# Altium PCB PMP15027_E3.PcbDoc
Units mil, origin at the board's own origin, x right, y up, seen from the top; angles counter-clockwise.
Board outline 3310 x 2510 mil, 4 copper layers (Top Layer, Inner Layer 1, Inner Layer 2, Bottom Layer), stack 61.2 mil thick; 79 components, 38 nets, 184 pads, 168 vias.
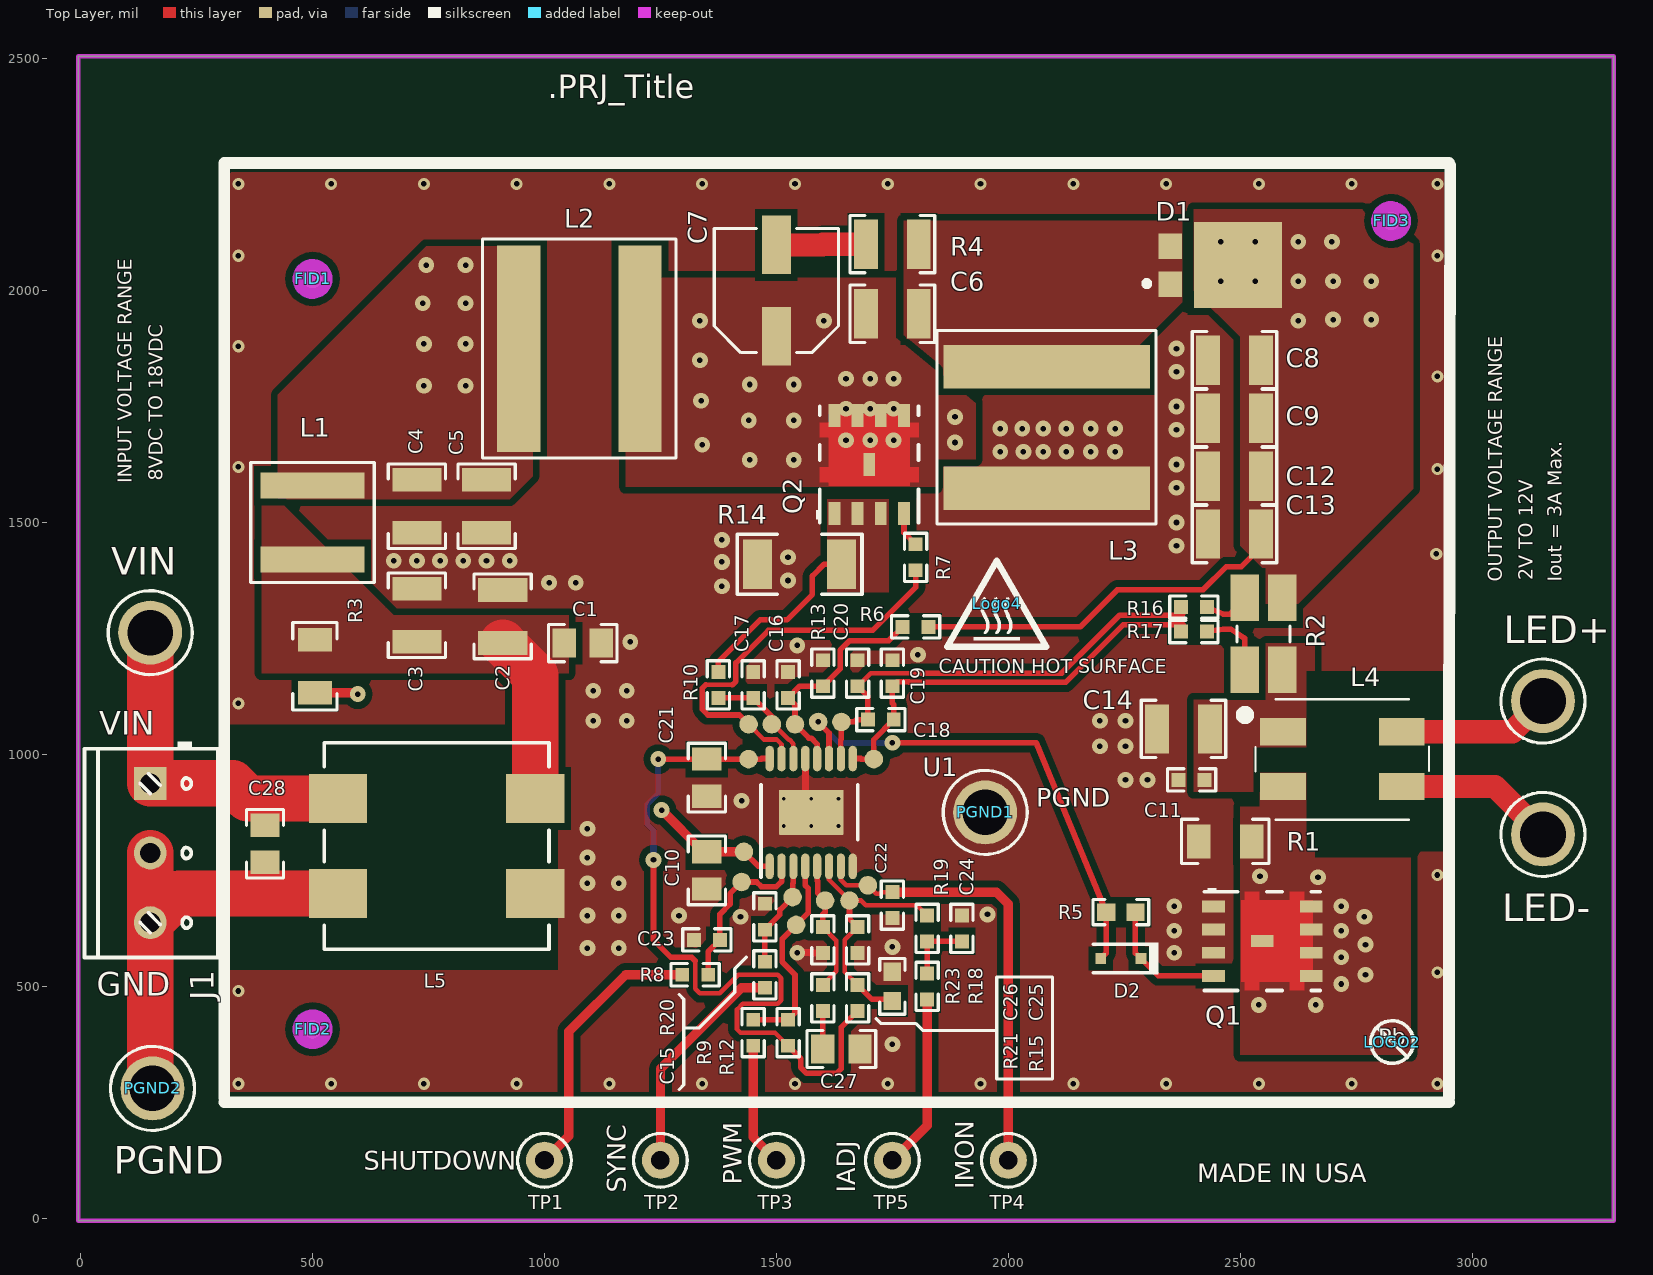
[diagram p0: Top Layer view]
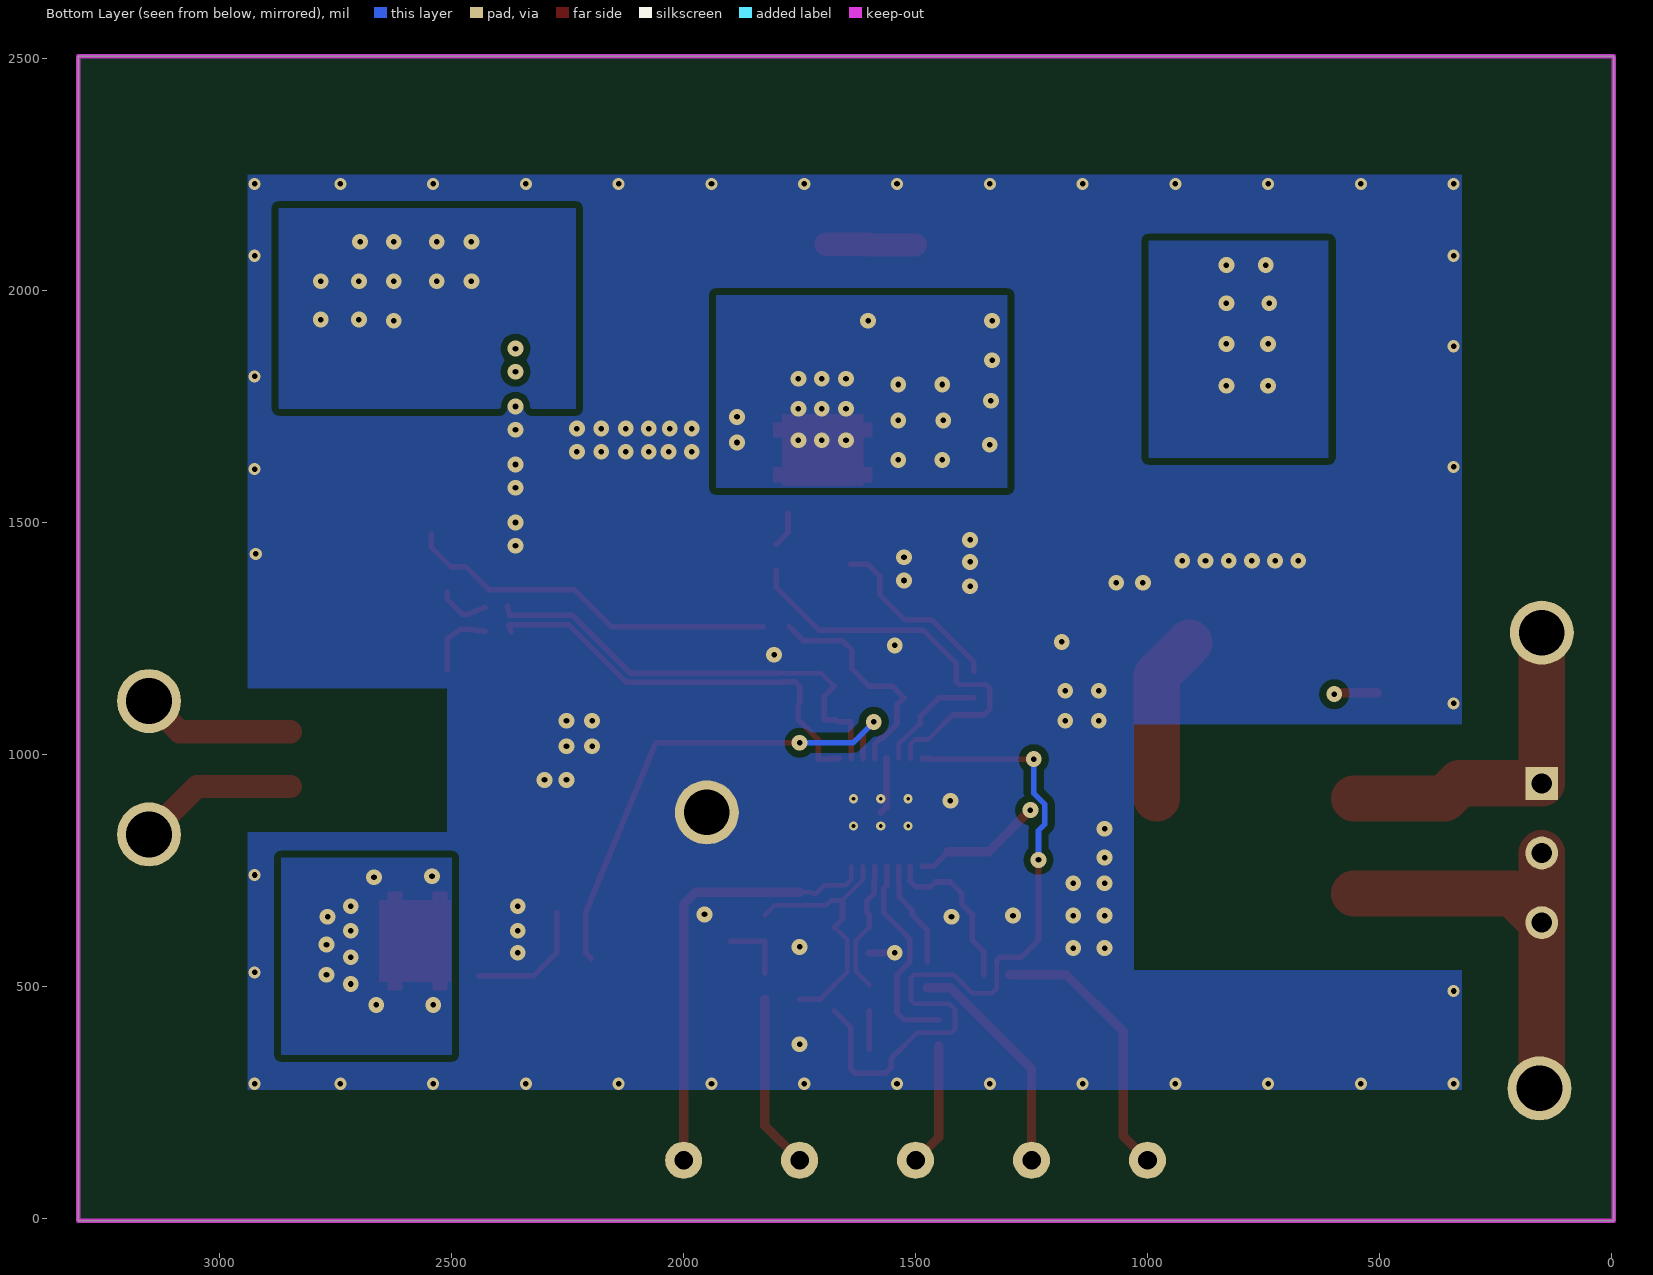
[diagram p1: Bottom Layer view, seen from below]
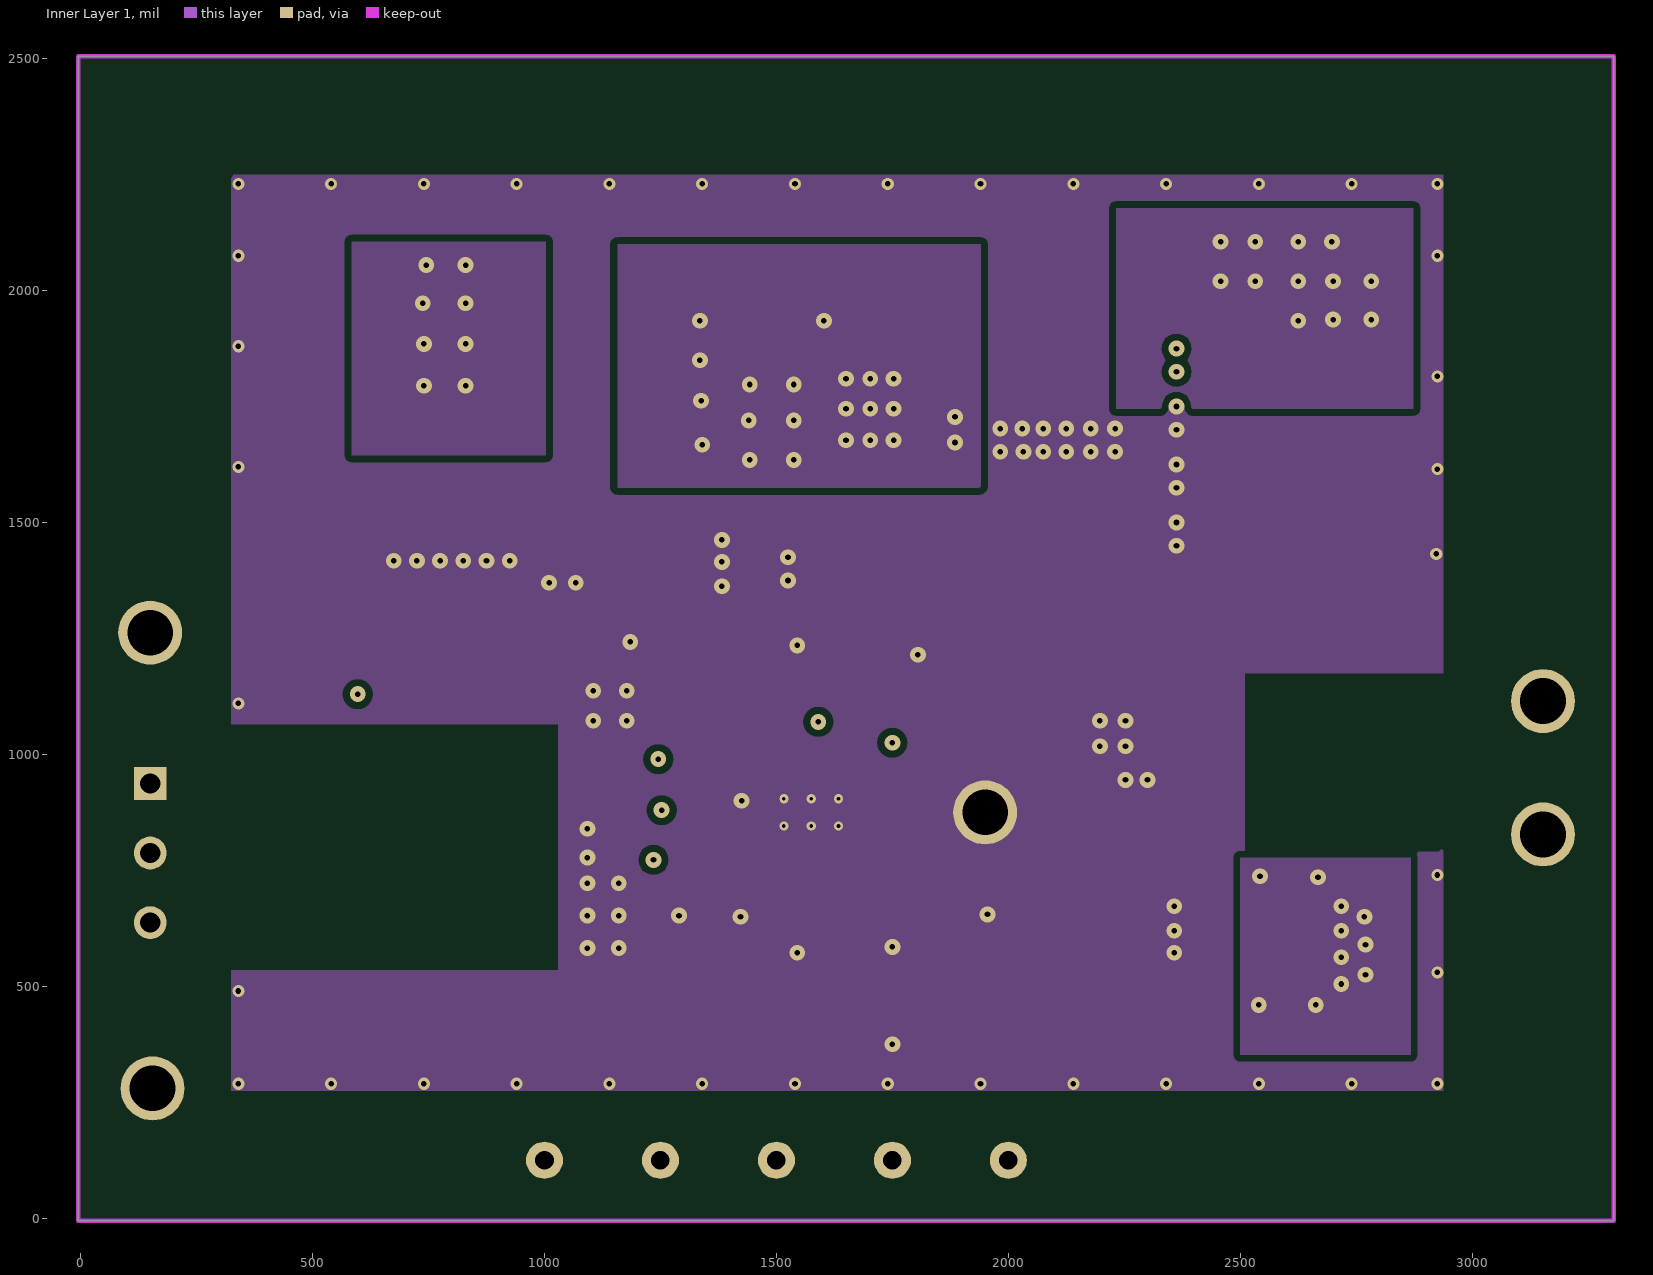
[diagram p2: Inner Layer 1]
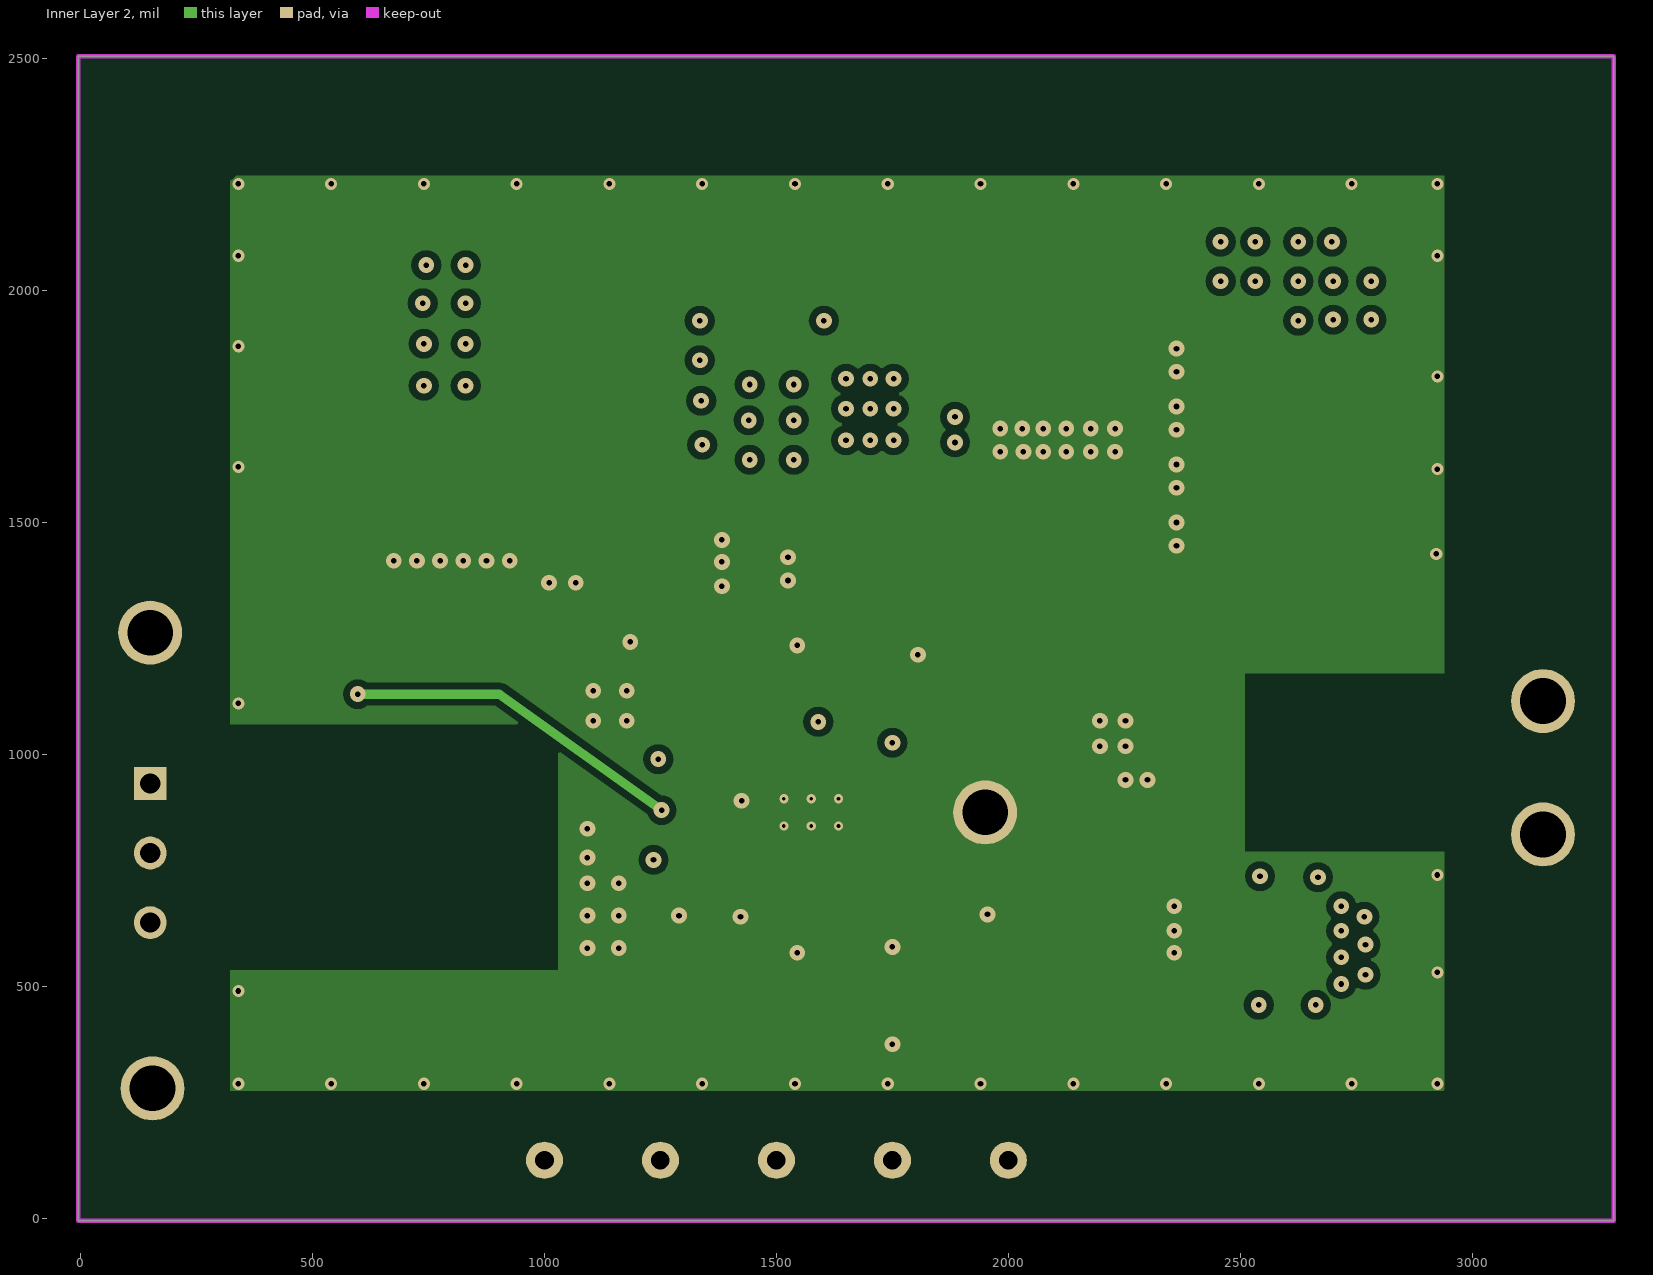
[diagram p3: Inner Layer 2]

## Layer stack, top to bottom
Top Solder: solder mask 0.4, Solder Resist, Dk 3.5
Top Layer: signal copper 1.4
Dielectric1: prepreg 8, Dk 4.2
Inner Layer 1: signal copper 2.8
Dielectric 3: core 36.8, Dk 4.2
Inner Layer 2: signal copper 2.8
Dielectric 2: prepreg 8, Dk 4.2
Bottom Layer: signal copper 1.4
Bottom Solder: solder mask 0.4, Solder Resist, Dk 3.5

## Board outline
-5,-5 -5,2505 3305,2505 3305,-5

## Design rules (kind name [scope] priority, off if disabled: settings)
AcuteAngle [All] p1: minimum=4.50000000000000E+0001 checktracksonly=FALSE
AssemblyTestPointUsage [All] p1: valid=2
Clearance Clearance_Keepouts [((IsTrack Or IsArc) And Not InPoly) And IsFree and IsKeepOut vs ((IsTrack Or IsArc) And Not InPoly) And IsFree and IsKeepOut] p1: gap=0
Clearance Clearance_BoardEdge_MountingHoles [OnCopper and InComponentClass('Mounting Holes') vs IsKeepOut] p2: gap=40
Clearance Clearance_BoardEdge_Poly [OnCopper and InPoly vs IsKeepOut] p3: gap=15
Clearance Clearance_BoardEdge [OnCopper and Not InComponentClass('Logo') and not InComponentClass('FiducialMark') and not InRegion(1000,500,4000,800) and Not IsKeepout vs IsKeepOut] p4: gap=25
Clearance Clearance_Poly [InPolygon] p5: gap=15
Clearance [All] p6: gap=7.87
ComponentClearance ComponentClearance_Logos [InComponentClass('Logo')] p1: gap=-1 collisioncheckmode=3 verticalgap=-1 showdistances=FALSE
ComponentClearance [All] p2: gap=5 collisioncheckmode=3 verticalgap=5 showdistances=FALSE
DiffPairsRouting [All] p1: maxlimit=100 minlimit=10 mostfreqgap=10 toplayer_minwidth=15 toplayer_maxwidth=15 toplayer_prefwidth=15 midlayer1_minwidth=15 midlayer1_maxwidth=15 midlayer1_prefwidth=15 midlayer2_minwidth=15 midlayer2_maxwidth=15 midlayer2_prefwidth=15 bottomlayer_minwidth=15 bottomlayer_maxwidth=15 bottomlayer_prefwidth=15 maxuncoupledlength=1000
FabricationTestPointUsage TestPointUsage [All] p1: valid=2 allowmultiple=FALSE
FabricationTestpoint Testpoint [All] p1: side=3 testpointundercomponent=TRUE minsize=40 maxsize=100 preferedsize=60 minholesize=0 maxholesize=40 preferedholesize=32 testpointgrid=1 allowsidetop=TRUE allowsidebottom=TRUE usegrid=TRUE gridtolerance=0.01
FanoutControl Fanout_LCC [IsLCC] p1: bgadir=Out bgaviamode=Centered fanoutstyle=Auto fanoutdirection=Alternating viagrid=1 // Fanout_LCC (Default Rule)
FanoutControl Fanout_BGA [IsBGA] p2: bgadir=Out bgaviamode=Centered fanoutstyle=Auto fanoutdirection=Alternating viagrid=1 // Fanout_BGA (Default Rule)
FanoutControl Fanout_Default [All] p4: bgadir=Out bgaviamode=Centered fanoutstyle=Auto fanoutdirection=Alternating viagrid=1 // Fanout_Default (Default Rule)
FanoutControl Fanout_Small [(CompPinCount < 5)] p5: bgadir=Out bgaviamode=Centered fanoutstyle=Auto fanoutdirection=OutThenIn viagrid=1 // Fanout_Small (Default Rule)
HoleSize [All] p1: absolutevalues=TRUE maxlimit=251 minlimit=7.87 maxpercent=80.000 minpercent=20.000
MinimumAnnularRing MinimumAnnularRing_U1 [InComponent('U1')] p1: minimumring=0
MinimumAnnularRing MinimumAnnularRing_ThermalPadVias [IsVia and InAnyComponent] p2: minimumring=2.5
MinimumAnnularRing [All] p3: minimumring=5
MinimumSolderMaskSliver MinimumSolderMaskSliver_Logo [InComponentClass('Logo') vs InComponentClass('Logo')] p1: minsoldermaskwidth=0.7
MinimumSolderMaskSliver [All] p2: minsoldermaskwidth=5
PlaneConnect [All] p1: planeconnectstyle=Relief reliefexpansion=10 reliefentries=4 reliefconductorwidth=10 reliefairgap=10
PolygonConnect [All] p1: connectstyle=Direct reliefconductorwidth=10 reliefentries=4 polygonreliefangle="90 Angle" airgapwidth=10
RoutingVias RoutingVias_U1_Q1 [InComponent('U1') OR InComponent('Q1')] p1: holewidth=28 width=50 viastyle="Through Hole" minholewidth=7.87 minwidth=15.75 maxholewidth=28 maxwidth=50
RoutingVias ThermalPadVias [IsVia and InAnyComponent] p2: holewidth=7.87 width=19.68 viastyle="Through Hole" minholewidth=7.87 minwidth=19.68 maxholewidth=12.99 maxwidth=23.62
RoutingVias [All] p3: holewidth=12 width=34 viastyle="Through Hole" minholewidth=7.87 minwidth=20 maxholewidth=40 maxwidth=65
SilkToBoardRegionClearance [Not ((IsComment or IsDesignator) And (Hide <> 'False')) and not InRegion(1000,500,4000,800)] p1:
SilkToSilkClearance SilkToSilkClearance_Pb-FreeLogo [(HasFootprint('Pb-Free_Overlay_Medium') OR HasFootprint('Pb-Free_Overlay_Small')) vs (HasFootprint('Pb-Free_Overlay_Medium') OR HasFootprint('Pb-Free_Overlay_Small'))] p1: silktosilkclearance=0
SilkToSilkClearance [All] p2: silktosilkclearance=3
SilkToSolderMaskClearance SilkToSolderMaskClearance_J1 [InComponent('J1')] p1: minsilkscreentomaskgap=-1 clearancetoexposedcopper=TRUE
SilkToSolderMaskClearance [IsPad] p2: minsilkscreentomaskgap=5 clearancetoexposedcopper=TRUE
SolderMaskExpansion [All] p1: expansion=0
Width [All] p1: maxlimit=100 minlimit=6 preferedwidth=10 toplayer_minwidth=7 toplayer_prefwidth=7 bottomlayer_minwidth=7 bottomlayer_prefwidth=7 minimp=50.000000 maximp=50.000000 favimp=50.000000 checkconnectedcopper=TRUE
15 further rules are at their usual default settings.

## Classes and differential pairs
component class PMP15027_E3: C1 C2 C3 C4 C5 C6 C7 C8 C9 C10 C11 C12 C13 C14 C15 C16 C17 C18 C19 C20 C21 C22 C23 C24 C25 C26 C27 C28 D1 D2 J1 L1 L2 L3 L4 L5 LED+ LED- Logo4 PGND1 PGND2 Q1 Q2 R1 R2 R3 R4 R5 R6 R7 R8 R9 R10 R12 R13 R14 R15 R16 R17 R18 R19 R20 R21 R23 TP1 TP2 TP3 TP4 TP5 U1 VIN
component class PMP15027_E3_Hardware: FID1 FID2 FID3 LOGO2 ZZ1 ZZ2 ZZ3 ZZ4
component class FiducialMark: FID1 FID2 FID3
component class AssemblyNote: ZZ1 ZZ2 ZZ3 ZZ4

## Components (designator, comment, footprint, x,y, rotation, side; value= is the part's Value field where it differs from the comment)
C1 "C2012X7R2A104K" 0805_HV 1082.5,1240 r0 top
C2 "C3225X7S2A475K200AE" 1210 910,1297.5 r90 top
C3 "CGA6P3X7S1H106K250AB" 1210 725,1300 r90 top
C4 "CGA6P3X7S1H106K250AB" 1210 725,1535 r270 top
C5 "CGA6P3X7S1H106K250AB" 1210 875,1535 r270 top
C6 "CGA6P3X7S1H106K250AB" 1210 1750,1950 r0 top
C7 "EEE-FK1H470XP" SM_RADIAL_D8 1500,2000 r90 top
C8 "CGA6P3X7S1H106K250AB" 1210 2487.5,1850 r0 top
C9 "CGA6P3X7S1H106K250AB" 1210 2487.5,1725 r0 top
C10 "C2012X7R2A104K" 0805_HV 1350,750 r90 top
C11 "C1608X8R2A103K" 0603_HV 2395,945 r180 top
C12 "CGA6P3X7S1H106K250AB" 1210 2487.5,1600 r0 top
C13 "CGA6P3X7S1H106K250AB" 1210 2487.5,1475 r0 top
C14 "C1210C104K5RACTU" 1210 2377.5,1055 r180 top
C15 "C1608C0G1H101J" 0603_HV 1475,525 r270 top
C16 "C1608C0G2A102J" 0603_HV 1525,1150 r90 top
C17 "C1608C0G2A102J" 0603_HV 1450,1150 r90 top
C18 "GRM188R72A104KA35D" 0603_HV 1725,1075 r0 top
C19 "C1608X8R2A103K" 0603_HV 1750,1175 r90 top
C20 "C1608X8R2A103K" 0603_HV 1675,1175 r90 top
C21 "C2012X7R1C225K" 0805_HV 1350,950 r270 top
C22 "C1608C0G1H100D" 0603_HV 1750,675 r270 top
C23 "C1608X8R1E104K" 0603_HV 1350,600 r180 top
C24 "C1608X8R1E104K" 0603_HV 1900,625 r90 top
C25 "C1608X8R1E104K" 0603_HV 1675,600 r270 top
C26 "GRM188R71C223KA01D" 0603_HV 1600,600 r270 top
C27 "GRM21BR71C184KA01L" 0805_HV 1640,365 r180 top
C28 "08055C104JAT2A" 0805_HV 397.5,807.5 r270 top
D1 "FSV8100V" TO-277A 2420.89,2055 r90 top
D2 "MMSZ5237BS-7-F" sod-323 2242.5,560 r180 top
FID1 "Fiducial" Fiducial10-20 500,2025 r0 top
FID2 "Fiducial" Fiducial10-20 500,407.5 r0 top
FID3 "Fiducial" Fiducial10-20 2825,2150 r0 top
J1 "1727023" Phoenix_1727023 150,787.5 r270 top
L1 "CLF7045T-3R3N" XAL6030 500,1500 r90 top
L2 "IHLP4040DZER100M8A" XAL1010 1075,1875 r0 top
L3 "IHLP4040DZER100M8A" XAL1010 2082.5,1705 r90 top
L4 "ACM7060-301-2PL-TL" IND_TDK_ACM7060 2720,990 r0 top
L5 "ACM1211-102-2PL-TL01" TDK_ACM1211 767.5,802.5 r90 top
LED+ "Suggest using a net name here" Keystone1502-2 3152.5,1115 r0 top
LED- "Suggest using a net name here" Keystone1502-2 3152.5,827.5 r0 top
LOGO2 "Pb-Free Symbol" Pb-Free_Overlay_Small 2827.5,380 r0 top (schematic designator Logo2)
Logo4 "CAUTION HOT SURFACE" IEC_HotSurface_Small 1975,1325 r0 top (schematic designator LOGO4)
PGND1 "PGND" Keystone1502-2 1950,875 r0 top
PGND2 "PGND" Keystone1502-2 155,280 r90 top
Q1 "SI7113DN-T1-GE3" PowerFLAT5x6_R 2547.5,597.5 r0 top
Q2 "STL8N10LF3" PowerFLAT5x6_R 1700,1625 r90 top
R1 "CRCW12060000Z0EA" 1206 2467.5,812.5 r0 top
R2 "LVK12R050DER" LVK20 2550,1255 r270 top
R3 "CRCW120610R0FKEA" 1206 505,1190 r90 top
R4 "ERJ-14BQF2R0U" 1210 1750,2100 r0 top
R5 "CRCW12062K00FKEA" 0603 2242.5,660 r0 top
R6 "CRCW0603150KFKEA" 0603_HV 1800,1275 r0 top
R7 "CRCW06034R70JNEA" 0603_HV 1800,1425 r90 top
R8 "CRCW06031K00JNEA" 0603_HV 1325,525 r0 top
R9 "CRCW06031K00JNEA" 0603_HV 1450,400 r90 top
R10 "CRCW0603100RFKEA" 0603_HV 1375,1150 r90 top
R12 "CRCW0603100KFKEA" 0603_HV 1525,400 r90 top
R13 "CRCW06033K74FKEA" 0603_HV 1600,1175 r270 top
R14 "CSRN2010FK15L0" 2010 1550,1410 r0 top
R15 "CRCW0603100KFKEA" 0603_HV 1675,475 r90 top
R16 "CRCW060310R0FKEA" 0603_HV 2400,1317.5 r0 top
R17 "CRCW060310R0FKEA" 0603_HV 2400,1265 r0 top
R18 "CRCW06031K00FKEA" 0603_HV 1825,500 r90 top
R19 "CRCW06031K00FKEA" 0603_HV 1825,625 r90 top
R20 "CRCW060320K0FKEA" 0603_HV 1475,650 r270 top
R21 "CRCW06030000Z0EA" 0603_HV 1600,475 r90 top
R23 "CRCW060343K2FKEA" 0603 1750,500 r270 top
TP1 "5003" Keystone5003 1000,125 r90 top
TP2 "5003" Keystone5003 1250,125 r90 top
TP3 "5003" Keystone5003 1500,125 r90 top
TP4 "5003" Keystone5003 2000,125 r90 top
TP5 "5003" Keystone5003 1750,125 r90 top
U1 "TPS92691QPWPRQ1" PWP0016J_N 1575,875 r90 top
VIN "Suggest using a net name here" Keystone1502-2 150,1262.5 r0 top
ZZ1 "This Assembly Note is for PCB labels only" AssemblyNoteLabel 382.5,3492.5 r0 top
ZZ2 "These assemblies are ESD sensitive, ESD precautions shall be observed." AssemblyNote 381,3387 r0 top
ZZ3 "These assemblies must be clean and free from flux and all contaminants. Use of no clean flux is not acceptable." AssemblyNote 387.5,3292.5 r0 top
ZZ4 "These assemblies must comply with workmanship standards IPC-A-610 Class 2, unless otherwise specified." AssemblyNote 391,3179.5 r0 top

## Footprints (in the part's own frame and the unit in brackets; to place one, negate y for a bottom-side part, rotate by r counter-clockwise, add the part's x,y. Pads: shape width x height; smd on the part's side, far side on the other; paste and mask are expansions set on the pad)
0603 [mm] "0603 from SM-752 data"
  rect 1x0.95 smd: 1(-0.8,0) 2(0.8,0)
  silkscreen extent -1.52,-0.69 1.52,0.69, body extent -0.87,-0.47 0.87,0.47, height 1
0603_HV [mil] "Ernesto recommended land pattern.  26 mil between pads."
  rect 30x30 smd: 1(-28,0) 2(28,0)
  silkscreen extent -52,-24 52,24, body extent -34,-19 34,19, height 39
0805_HV [mil] "0805 with 30mil clearance between pads"
  rect 50x63 smd: 1(-40,0) 2(40,0)
  silkscreen extent -74,-40 74,40, body extent -43,-29 43,29, height 57
1206 [mm] "1206 from SM-752 data"
  rect 1.3x1.85 smd: 1(-1.45,0) 2(1.45,0)
  silkscreen extent -2.4,-1.21 2.4,1.21, body extent -1.7,-0.9 1.7,0.9, height 1.35
1210 [mm] "1210 from SM-752 data"
  rect 1.3x2.7 smd: 1(-1.45,0) 2(1.45,0)
  silkscreen extent -2.32,-1.57 2.32,1.57, body extent -1.7,-1.35 1.7,1.35, height 1.35
2010 [mm] "Chip Capacitor, Body 5.08x2.54mm, IPC Medium Density"
  rect 1.6x2.7 smd: 1(-2.3,0) 2(2.3,0)
  silkscreen extent -3.42,-1.65 3.42,1.65, body extent -2.73,-1.45 2.73,1.45, height 1.66
AssemblyNote [mil] "Assembly Note"
AssemblyNoteLabel [mil] "Assembly Note for PCB Labels"
Fiducial10-20 [mm]
  round 1 smd mask+0.5: 1(0,0)
  Top Layer keep-out circle w1.178: c0,0 r0.5
IEC_HotSurface_Small [mil]
  silkscreen extent -107,-93 107,92
IND_TDK_ACM7060 [mm] "TDK Common Mode EMI Filter 7mmx6mm"
  rect 2.5x1.5 smd: 1(-3.25,1.5) 2(-3.25,-1.5) 3(3.25,-1.5) 4(3.25,1.5)
  silkscreen extent -5.58,-3.32 4.75,3.27, body extent -3.6,-3.12 3.6,3.07, height 3.55
Keystone1502-2 [mm] "Double Turret"
  round 3.5 hole 2.5: 1(0,0)
  silkscreen extent -2.3,-2.3 2.3,2.3, body extent -1.6,-1.6 1.59,1.6, height 5.62
Keystone5003 [mil] "For Keystone 500x miniature loop terminals"
  round 80 hole 40: 1(0,0)
  silkscreen extent -58,-58 58,58, body extent -49,-49 49,49, height 182
LVK20 [mm] "Ohmite"
  rect 2.55x1.55 smd: 1(-2.1,1.025) 2(1.85,1.025) 3(-2.1,-1.025) 4(1.85,-1.025)
  silkscreen extent -0.55,-1.45 0.3,1.45, body extent -2.6,-1.35 2.6,1.35, height 0.65
Pb-Free_Overlay_Small [mil]
  silkscreen extent -46,-46 46,46
Phoenix_1727023 [mm] "Phoenix Contact"
  rect 1.8x1.8 hole 1.1: 1(-3.81,0)
  round 1.8 hole 1.1: 2(0,0) 3(3.81,0)
  silkscreen extent -6.1,-3.6 5.72,3.7, body extent -5.71,-3.6 5.72,3.7, height 8.5
PowerFLAT5x6_R [mm] "SMD, 8-Leads, Body 6.15x5.2mm, Pitch 1.27mm"
  rect 1.25x0.65 smd: 1(-2.675,1.905) 2(-2.675,0.635) 3(-2.675,-0.635) 4(-2.675,-1.905) 5(2.675,-1.905) 6(2.675,-0.635) 7(2.675,0.635) 8(2.675,1.905) 9(0,0)
  Top Layer region: -0.96,2.7 -0.96,2.225 -1.15,2.225 -1.15,-2.225 -0.96,-2.225 -0.96,-2.7 -0.16,-2.7 -0.16,-2.225 1.49,-2.225 1.49,-2.7 2.29,-2.7 2.29,-2.225 2.75,-2.225 2.75,2.225 2.29,2.225 2.29,2.7 1.49,2.7 1.49,2.225 -0.16,2.225 -0.16,2.7
  silkscreen extent -3.17,-2.7 3.17,2.9, body extent -3.17,-2.7 3.17,2.7, height 1.01
PWP0016J_N [mm] "TSOP, 16-Leads, Body 5x4.4mm, Pitch 0.65mm, Exposed Pad, IPC Medium Density"
  oval 1.4x0.45 smd: 1(-2.95,2.275) 2(-2.95,1.625) 3(-2.95,0.975) 4(-2.95,0.325) 5(-2.95,-0.325) 6(-2.95,-0.975) 7(-2.95,-1.625) 8(-2.95,-2.275) 9(2.95,-2.275) 10(2.95,-1.625) 11(2.95,-0.975) 12(2.95,-0.325) 13(2.95,0.325) 14(2.95,0.975) 15(2.95,1.625) 16(2.95,2.275)
  rrect4% 2.46x3.55 smd: 17(0,0)
  silkscreen extent -3.55,-2.55 1.5,2.75, body extent -3.21,-2.5 3.21,2.5, height 1
SM_RADIAL_D8 [mm] "6.3 x 7.7mm:  Panasonic D8"
  rect 3.2x1.6 smd: 1(-2.5,0) 2(2.5,0)
  silkscreen extent -3.4,-3.4 3.4,3.4, body extent -3.4,-3.4 3.4,3.4, height 8.01
sod-323 [mm] "NXP recommended land pattern"
  rect 0.6x0.6 smd paste-0.05: 1(-1.1,0) 2(1.1,0)
  silkscreen extent -2.06,-0.86 1.53,0.86, body extent -1.3,-0.67 1.3,0.68, height 1.1
TDK_ACM1211 [mm] "SMT, 4-Leads, Body 12x11mm"
  rect 2.7x3.2 smd: 1(-2.6,5.4) 2(2.6,5.4) 3(2.6,-5.4) 4(-2.6,-5.4)
  silkscreen extent -5.65,-6.15 5.65,6.15, body extent -5.65,-6.15 5.65,6.15, height 6
TO-277A [mm] "Vishay"
  rect 1.4x1.27 smd: 1(-1.04,1.83) 2(1.04,1.83)
  rect 4.72x4.8 smd: 3(0,-1.883)
  silkscreen extent -1.17,2.96 -0.87,3.26, body extent -2.35,-4.2 2.4,2.45, height 1.2
XAL1010 [mm] "COILCRAFT"
  rect 2.38x11.31 smd: 1(-3.325,0) 2(3.325,0)
  silkscreen extent -5.3,-6 5.3,6, body extent -5.25,-5.9 5.25,5.9, height 10
XAL6030 [mil] "Coilcraft recommended land pattern Document 887-4 Revised 11/20/12"
  rect 56x224 smd: 1(-79.5,0) 2(79.5,0)
  silkscreen extent -129,-133 129,133, body extent -129,-133 129,133, height 122

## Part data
C1 C10: "CAP, CERM, 0.1 µF, 100 V, +/- 10%, X7R, 0805"
C2: "CAP, CERM, 4.7 µF, 100 V, +/- 10%, X7S, 1210"
C3 C4 C5 C6 C8 C9 C12 C13: "CAP, CERM, 10 µF, 50 V, +/- 10%, X7S, AEC-Q200 Grade 1, 1210"
C7: "CAP, AL, 47 µF, 50 V, +/- 20%, 0.68 ohm, SMD"
C11 C19 C20: "CAP, CERM, 0.01 µF, 100 V, +/- 10%, X8R, 0603"
C14: "CAP, CERM, 0.1 µF, 50 V, +/- 10%, X7R, 1210"
C15: "CAP, CERM, 100 pF, 50 V, +/- 5%, C0G/NP0, 0603"
C16 C17: "CAP, CERM, 1000 pF, 100 V, +/- 5%, C0G/NP0, 0603"
C18: "CAP, CERM, 0.1 µF, 100 V, +/- 10%, X7R, 0603"
C21: "CAP, CERM, 2.2 µF, 16 V, +/- 10%, X7R, 0805"
C22: "CAP, CERM, 10 pF, 50 V, +/- 5%, C0G/NP0, 0603"
C23 C24 C25: "CAP, CERM, 0.1 µF, 25 V, +/- 10%, X8R, 0603"
C26: "CAP, CERM, 0.022 µF, 16 V, +/- 10%, X7R, 0603"
C27: "CAP, CERM, 0.18 µF, 16 V, +/- 10%, X7R, 0805"
C28: "CAP, CERM, 0.1 µF, 50 V, +/- 5%, X7R, 0805"
D1: "Diode, Schottky, 100 V, 8 A, AEC-Q101, TO-277A"
D2: library part BAT54HT1G, "Diode, Schottky, 30 V, 0.2 A, SOD-323"
FID1 FID2 FID3: "Fiducial mark.  There is nothing to buy or mount."
J1: "Terminal Block Receptacle, 3x1, 3.81mm, R/A, TH"
L1: library part XAL6030-332MEB, "Inductor, Shielded, Composite, 3.3 µH, 9.8 A, 0.02 ohm, SMD"
L2 L3: library part XAL1010-103MEB, "Inductor, Shielded, Composite, 10 µH, 15.5 A, 0.01 ohm, SMD"
L4: library part INDUCTOR_COUPLED, "CMC 4A 2LN 700 OHM SMD"
L5: "Coupled inductor, 6 A, 0.014 ohm, SMD"
LED+ LED- PGND1 PGND2 VIN: library part 1502-2, "Terminal, Turret, TH, Double"
LOGO2: library part Pb-Free
Logo4: library part IEC_HotSurface, "IEC 61010-1 Hot Surface Warning"
Q1: library part STL8N10LF3, "MOSFET, N-CH, 100 V, 20 A, AEC-Q101, 8-PowerVDFN"
Q2: "MOSFET, N-CH, 100 V, 20 A, AEC-Q101, 8-PowerVDFN"
R1: "RES, 0, 5%, 0.25 W, 1206"
R2: library part LVK20R050DER, "RES, 0.05, 0.5%, 0.75 W, 2010 sense"
R3: "RES, 10.0, 1%, 0.25 W, 1206"
R4: "RES, 2.00, 1%, 0.5 W, AEC-Q200 Grade 0, 1210"
R5: library part CRCW06031K00FKEA, "RES, 1.00 k, 1%, 0.1 W, 0603"
R6: "RES, 150 k, 1%, 0.1 W, 0603"
R7: library part CRCW06030000Z0EA, "RES, 0, 5%, 0.1 W, 0603"
R8 R9: "RES, 1.0 k, 5%, 0.1 W, 0603"
R10: "RES, 100, 1%, 0.1 W, 0603"
R12 R15: "RES, 100 k, 1%, 0.1 W, 0603"
R13: "RES, 3.74 k, 1%, 0.1 W, 0603"
R14: "RES, 0.015, 1%, 1 W, 2010"
R16 R17: "RES, 10.0, 1%, 0.1 W, 0603"
R18 R19: "RES, 1.00 k, 1%, 0.1 W, 0603"
R20: library part CRCW060322K6FKEA, "RES, 22.6 k, 1%, 0.1 W, 0603"
R21: "RES, 0, 5%, 0.1 W, 0603"
R23: library part CRCW060338K3FKEA, "RES, 38.3 k, 1%, 0.1 W, 0603"
TP1 TP2 TP3 TP4 TP5: "Test Point, Miniature, Orange, TH"
U1: "Multi-Topology LED Driver with Rail-to-Rail Current Sense Amplifier, PWP0016J"
ZZ1: library part AssemblyNoteLabel
ZZ2 ZZ3 ZZ4: library part AssemblyNote

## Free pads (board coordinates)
  round 40 smd: 1(1710,990) 2(1640,1070) 3(1590,1070) 4(1540,1065) 5(1490,1065) 6(1440,990) 6(1440,1065) 7(1430,790) 8(1425,725) 9(1535,692.5) 10(1542.5,632.5) 11(1605,685) 12(1657.5,685) 13(1697.13,717.87)

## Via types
v1: diameter 34, hole 12, Top Layer to Bottom Layer, tented both sides, 123 vias
v2: diameter 26, hole 12, Top Layer to Bottom Layer, tented both sides, 39 vias
v3: diameter 19.68, hole 8, Top Layer to Bottom Layer, 6 vias

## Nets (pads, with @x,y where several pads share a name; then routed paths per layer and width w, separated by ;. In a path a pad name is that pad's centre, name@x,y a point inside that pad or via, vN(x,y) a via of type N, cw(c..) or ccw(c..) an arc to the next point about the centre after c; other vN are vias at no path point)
IADJ: C25.1 pad.12 R15.2 R19.2 R23.2 U1.6 | length 572.5
  Top Layer w10: U1.6 1613.39,729.72 pad.12@1657.5,685.61 ; pad.12 1682.5,685 1692.63,674.87 1803.13,674.87 R19.2 ; R15.2 1647.13,530.87 1647.13,600.13 C25.1
  Top Layer w12: pad.12 1657.5,645.5 C25.1 ; R15.2 1706,472 R23.2@1750,472
IMON: C22.1 pad.13 TP4.1 U1.7 | length 967
  Top Layer w10: U1.7 1638.98,729.41 1650.51,717.87 pad.13 1715,700 1722.5,700 1725.5,703 C22.1
  Top Layer w20: C22.1 1974.5,703 2000,677.5 TP4.1
NetC1_1: C1.1 C2.1 C3.1 L1.1 L5.3 R3.2 | length 364.6
  Top Layer w100: C2.1 980.1,1170.32 L5.3
NetC4_1: C4.1 C5.1 L1.2 L2.1
  other v1: 740,1795 830,1795 740,1885 830,1885 737.5,1972.5 830,1972.5 745,2055 830,2055
NetC6_1: C6.1 C7.1 L2.2 Q2.5 Q2.6 Q2.7 Q2.8 Q2.9
  other v1: 1442.5,1635 1537.5,1635 1340,1667.5 1885,1672.5 1650,1677.5 1702.5,1677.5 1752.5,1677.5 1440.22,1720 1537.5,1720 1885,1727.5 1650,1745 1702.5,1745 1752.5,1745 1337.5,1762.5 1442.5,1797.5 1537.5,1797.5 1650,1810 1702.5,1810 1752.5,1810 1335,1850 1335,1935 1602.5,1935
NetC6_2: C6.2 D1.1 D1.2 L3.2 R4.2
NetC7_2: C7.2 R4.1 | length 193.6
  Top Layer w50: C7.2 1599.07,2098.43 1600.65,2100 R4.1
NetC8_2: C8.2 C9.2 C12.2 C13.2 D1.3 R2.1 R6.2 | length 815.8
  Top Layer w12: R6.2 2155,1275 2235,1355 2420,1355 2470,1405 2502.5,1405 2544.59,1447.09 C13.2
  other v1: 2625,1935 2700,1937.5 2782.5,1937.5 2457.5,2020 2532.5,2020 2625,2020 2700,2020 2782.5,2020 2457.5,2105 2532.5,2105 2625,2105 2697.5,2105
NetC10_2: C10.2 pad.7 R3.1 U1.1 | length 1111.9
  Top Layer w12: pad.7 1461.14,758.86 U1.1
  Top Layer w20: R3.1 594.59,1132.91 v1(597.5,1130) ; v1(1252.5,880) 1342.5,790 C10.2 1392.5,790 pad.7
  Inner Layer 2 w20: v1(597.5,1130) 902.5,1130 v1(1252.5,880)
NetC11_1: C11.1 C14.1 L4.1 R2.2
NetC15_2: C15.2 TP2.1 | length 494.8
  Top Layer w20: TP2.1 1250,322.5 1424.5,497 C15.2
NetC16_1: C16.1 pad.4 R6.1 R13.2 U1.12 | length 493.9
  Top Layer w12: U1.12 1587.8,1022.2 1575,1035 1570,1035 pad.4 1540,1107 C16.1 1550,1147 R13.2 1637.5,1184.5 1637.5,1225 1657.5,1245 1742,1245 R6.1
NetC17_1: C17.1 pad.5 R10.1 U1.14 | length 244.7
  Top Layer w10: pad.5 1492.78,1065 1526.39,1031.39 1528.61,1031.39 1536.61,1023.39 U1.14
  Top Layer w12: R10.1 C17.1 1490,1082 pad.5
NetC18_1: C18.1 C20.1 pad.2 R16.1 U1.10 | length 1003.1
  Top Layer w10: C20.1 1703.13,1175.13 1794.87,1175.13
  Top Layer w12: U1.10 1638.98,1031.48 1640,1032.5 pad.2 1667.5,1070 1672.5,1075 C18.1 1697,1125 C20.1 ; 1794.87,1175.13 2115.13,1175.13 2240,1300 2374.5,1300 R16.1@2380,1320
NetC18_2: C18.2 C19.1 pad.1 R17.1 U1.9 | length 920.7
  Top Layer w12: U1.9 1681.36,991.14 1682.5,990 pad.1 1710,1032 C18.2 1753,1107 1750,1110 C19.1 1759.25,1156.25 1785.64,1156.25 1786.64,1155.25 2123.36,1155.25 2248.11,1280 2377,1280 R17.1
NetC24_1: C24.1 R18.2 R19.1 | length 144
  Top Layer w12: R18.2 R19.1 C24.1
NetC26_1: C26.1 pad.11 R21.2 U1.5 | length 289.3
  Top Layer w10: R21.2 1629.25,532.25 1629.25,598.75 C26.1
  Top Layer w12: U1.5 1587.8,727.2 1588.75,726.25 1588.75,701.25 pad.11 1605,660 1600,655 C26.1
NetC27_2: C27.2 R21.1 | length 82
  Top Layer w12: C27.2 1600,415 R21.1
NetC28_1: C28.1 J1.1 L5.2 VIN.1 | length 743.4
  Top Layer w100: VIN.1 J1.1 327.5,937.5 360,905 554.76,905 L5.2
NetC28_2: C28.2 J1.2 J1.3 L5.1 PGND2.1 | length 940.4
  Top Layer w100: J1.2 J1.3 ; PGND2.1 150,285 J1.3 ; L5.1 212.64,700.14 J1.3
NetD2_1: D2.1 Q1.4 R5.2 | length 276.8
  Top Layer w12: R5.2 2274,571.81 D2.1 2323.31,522.5 Q1.4
NetD2_2: D2.2 pad.3 R5.1 U1.11 | length 1077.1
  Top Layer w12: v1(1590,1070) 1613.39,1046.61 U1.11 ; v1(1750,1025) 2060,1025 R5.1 2211,571.81 D2.2
  Bottom Layer w12: v1(1590,1070) 1635,1025 v1(1750,1025)
NetL4_2: L4.2 Q1.5 Q1.6 Q1.7 Q1.8 Q1.9 R1.2
  other v1: 2540,460 2662.5,460 2717.5,505 2770,525 2717.5,562.5 2770,590 2717.5,620 2767.5,650 2717.5,672.5 2667.5,735 2542.5,737.5
NetL4_3: L4.3 LED-.1 | length 347.4
  Top Layer w50: L4.3 3049.06,930.94 LED-.1
NetL4_4: L4.4 LED+.1 | length 331.9
  Top Layer w50: L4.4 3086.56,1049.06 LED+.1
NetQ2_1: Q2.1 Q2.2 Q2.3 R10.2 R14.2 | length 397.8
  Top Layer w12: R10.2 1375,1200 1465,1290 1522.5,1290 1577.5,1345 1577.5,1384.67 1602.83,1410 R14.2
NetQ2_4: Q2.4 R7.2 | length 77
  Top Layer w12: Q2.4 1775,1478 R7.2
NetR2_3: R2.3 R16.2 | length 112.7
  Top Layer w12: R16.2 2463,1302.5 2477.5,1302.5 2509.94,1334.94 R2.3@2509.94,1349.13
NetR2_4: R2.4 R17.2 | length 156.2
  Top Layer w12: R17.2 2463,1270 2480,1270 2509.94,1250.06 R2.4
NetR7_1: pad.6@1440,1065 R7.1 U1.15 | length 888.4
  Top Layer w10: 1347.5,1150 1405,1150 ; pad.6@1440,1065 1472.87,1032.13 1500.37,1032.13 1511.02,1021.48 U1.15
  Top Layer w12: 1347.5,1150 1340,1142.5 1340,1097.5 1352.5,1085 1420,1085 pad.6@1440,1065 ; 1405,1150 1412.5,1157.5 1412.5,1197.5 1482.5,1267.5 1707.5,1267.5 1800,1360 R7.1
NetR8_1: R8.1 TP1.1 | length 594.5
  Top Layer w20: TP1.1 1052.5,177.5 1052.5,402.5 1175,525 R8.1
NetR9_1: R9.1 TP3.1 | length 267.7
  Top Layer w20: R9.1 1450,175 TP3.1
NetR18_1: R18.1 TP5.1 | length 378.1
  Top Layer w20: TP5.1 1825,200 R18.1
PGND: C1.2 C2.2 C3.2 C4.2 C5.2 C8.1 C9.1 C10.1 C11.2 C12.1 C13.1 C14.2 C16.2 C17.2 C19.2 C20.2 C21.2 C22.2 C23.2 C24.2 C25.2 C26.2 C27.1 L3.1 L5.4 PGND1.1 Q1.1 Q1.2 Q1.3 R1.1 R13.1 R14.1 R20.1 R23.1 U1.8 U1.13 U1.17 | length 176.6
  Top Layer w15: v1(1545,572.5) 1572.5,572.5 1573,572 C26.2 ; U1.13 1562.2,887.8 U1.17
  other v1: 1750,375 2357.5,572.5 1092.5,582.5 1160,582.5 1750,585 2357.5,620 1422.5,650 1092.5,652.5 1160,652.5 1290,652.5 1955,655 2357.5,672.5 1092.5,722.5 1160,722.5 1092.5,777.5 1092.5,840 1425,900 2252.5,945 2300,945 2197.5,1017.5 2252.5,1017.5 1105,1072.5 1177.5,1072.5 2197.5,1072.5 2252.5,1072.5 1105,1137.5 1177.5,1137.5 1805,1215 1545,1235 1185,1242.5 1382.5,1362.5 1010,1370 1067.5,1370 1525,1375 1382.5,1415 675,1417.5 725,1417.5 775,1417.5 825,1417.5 875,1417.5 925,1417.5 1525,1425 2362.5,1450 1382.5,1462.5 2362.5,1500 2362.5,1575 2362.5,1625 1982.5,1652.5 2032.5,1652.5 2075,1652.5 2125,1652.5 2177.5,1652.5 2230,1652.5 2362.5,1700 1982.5,1702.5 2030,1702.5 2075,1702.5 2125,1702.5 2177.5,1702.5 2230,1702.5 2362.5,1750 2362.5,1825 2362.5,1875
  other v2: 340,290 540,290 740,290 940,290 1140,290 1340,290 1540,290 1740,290 1940,290 2140,290 2340,290 2540,290 2740,290 2925,290 340,490 2925,530 2925,740 340,1110 2922.5,1432.5 2925,1615 340,1620 2925,1815 340,1880 340,2075 2925,2075 340,2230 540,2230 740,2230 940,2230 1140,2230 1340,2230 1540,2230 1740,2230 1940,2230 2140,2230 2340,2230 2540,2230 2740,2230 2925,2230
  other v3: 1515.94,845.47 1575,845.47 1634.06,845.47 1515.94,904.53 1575,904.53 1634.06,904.53
PWM: pad.10 R9.2 R12.2 U1.4 | length 449.6
  Top Layer w12: R9.2 R12.2 1540,443 1540,525 1512.5,552.5 1512.5,602.5 pad.10 1568.87,658.87 1568.87,711.13 1562.2,717.8 U1.4
SHUTDOWN: C23.1 pad.8 R8.2 U1.2 | length 357.4
  Top Layer w12: R8.2 1353,575 C23.1 1378,655.5 1400,677.5 1400,700 pad.8 1457.5,725 1467.5,715 1500,715 1511.02,726.02 U1.2
SYNC: C15.1 pad.9 R20.2 U1.3 | length 231.4
  Top Layer w12: C15.1 R20.2 1507.5,654.5 1507.5,665 pad.9 1535,721.77 1536.61,723.39 U1.3
VCC: C21.1 pad.6@1440,990 R12.1 R15.1 U1.16 | length 1635.8
  Top Layer w10: 1325,555 1325,495 1335,485 1377.5,485 1417.5,525 1502.5,525 1510,517.5 1510,470 1502.5,462.5 1427.5,462.5 1415,450 1415,407.5 1422.5,400 1497,400 R12.1
  Top Layer w12: v1(1235,772.5) 1235,600 1272.5,562.5 1317.5,562.5 1325,555 ; v1(1245,990) C21.1 1440,990 1467.5,990 1468.64,991.14 U1.16 ; R12.1 1552.5,344.5 1552.5,325 1565,312.5 1630,312.5 1640,322.5 1640,412 R15.1
  Bottom Layer w12: v1(1235,772.5) 1235,835.75 1221.63,849.13 1221.63,892.79 1245,916.16 v1(1245,990)
pads on no net: FID1.1 FID2.1 FID3.1

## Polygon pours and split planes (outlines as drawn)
PGND on Top Layer "PGND_L01_P103" (solid, remove dead copper, pour order 103): 322.5,2252.5 325,2255 2940,2255 2940,272.5 322.5,272.5
NetQ2_1 on Top Layer "NETQ2_1_L01_P050" (solid, remove dead copper, pour order 50): 1610,1550 1610,1350 1742.5,1350 1742.5,1550
NetC8_2 on Top Layer "NETC8_2_L01_P044" (solid, remove dead copper, pour order 44): 2400,2175 2872.5,2175 2872.5,1572.5 2625,1325 2552.5,1325 2550,1327.5 2550,1400 2525,1425 2500,1450 2500,1900 2400,2000
NetC6_2 on Top Layer "NETC6_2_L01_P042" (solid, remove dead copper, pour order 42): 2375,1975 2200,1800 1877.5,1800 1775,1902.5 1775,2150 2375,2150
NetC6_1 on Top Layer "NETC6_1_L01_P040" (solid, remove dead copper, pour order 40): 1757.5,2027.5 1252.5,2027.5 1175,1950 1175,1577.5 1500,1577.5 1930,1577.5 1930,1757.5 1757.5,1898.45
NetC4_1 on Top Layer "NETC4_1_L01_P038" (solid, remove dead copper, pour order 38): 425,1550 425,1775 745,2095 975,2095 975,1600 925,1550
NetC1_1 on Top Layer "NETC1_1_L01_P034" (solid, remove dead copper, pour order 34): 390,1175 1052.5,1175 1052.5,1300 675,1300 390,1585
NetC11_1 on Top Layer "Top Layer-No Net 4" (solid, pour order 97): 2400,920 2400,1117.5 2555,1117.5 2555,1240 2660,1240 2660,1015 2527.5,1015 2527.5,920
NetL4_2 on Top Layer "Top Layer-No Net 5" (solid, pour order 101): 2542.5,960 2542.5,887.5 2500,887.5 2500,352.5 2870,352.5 2867.5,355 2867.5,777.5 2660,777.5 2660,960
NetC8_2 on Bottom Layer "Bottom Layer-No Net" (solid, pour order 65): 2232.5,2177.5 2872.5,2177.5 2872.5,1747.5 2875,1745 2232.5,1745 2232.5,2177.5
NetC6_1 on Bottom Layer "Bottom Layer-No Net 1" (solid, pour order 31): 1930,1575 1302.5,1575 1302.5,1990 1930,1990
PGND on Bottom Layer "Bottom Layer-No Net 2" (solid, pour order 79): 322.5,2250 2940,2250 2940,277.5 2942.5,275 2940,277.5 322.5,277.5
NetC4_1 on Bottom Layer "Bottom Layer-No Net 4" (solid, pour order 29): 997.5,2107.5 997.5,1640 610,1640 610,2107.5
NetL4_2 on Bottom Layer "Bottom Layer-No Net 5" (solid, pour order 28): 2500,777.5 2867.5,777.5 2867.5,352.5 2500,352.5 2500,777.5
NetC8_2 on Inner Layer 1 "Inner Layer 1-No Net 1" (solid, pour order 63): 2232.5,2177.5 2872.5,2177.5 2872.5,1745 2232.5,1745
NetC6_1 on Inner Layer 1 "Inner Layer 1-No Net 2" (solid, pour order 67): 1157.5,2100 1940,2100 1940,1577.5 1937.5,1575 1157.5,1575 1157.5,2100
PGND on Inner Layer 1 "Inner Layer 1-No Net 3" (solid, pour order 75): 322.5,2250 2937.5,2250 2937.5,275 325,275 325,2242.5 327.5,2245
NetC4_1 on Inner Layer 1 "Inner Layer 1-No Net 5" (solid, pour order 30): 585,2105 1002.5,2105 1002.5,1645 585,1645
NetL4_2 on Inner Layer 1 "Inner Layer 1-No Net" (solid, pour order 27): 2500,777.5 2867.5,777.5 2867.5,352.5 2500,352.5 2500,777.5
NetC6_1 on Bottom Solder "Bottom Solder-No Net" (solid): 1377.5,1850 1802.5,1850 1802.5,1612.5 1377.5,1612.5
NetC8_2 on Bottom Solder "Bottom Solder-No Net" (solid): 2400,2175 2752.5,2175 2752.5,1960 2400,1960
PGND on Inner Layer 2 "Inner Layer 2-No Net" (solid, pour order 73): 327.5,2240 335,2247.5 2940,2247.5 2940,277.5 2937.5,275 322.5,275 322.5,2240 327.5,2245
NetL4_2 on Top Solder "Top Solder-No Net" (solid): 2637.5,705 2795,705 2795,490 2637.5,490
PGND on Top Solder "Top Solder-No Net" (solid): 2467.5,685 2467.5,560 2340,560 2340,685

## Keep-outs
Keep-Out Layer:
  the board outline again, w10
  text ".Layer_Name" at 377,-983.49 h60

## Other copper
Top Layer:
  pour cut-out: 300,1065 1030,1065 1030,535 300,535
  pour cut-out: 2642.5,1180 2967.5,1180 2967.5,790 2642.5,790
  text ".Layer_Name" at 377,-983.49 h60
Inner Layer 1:
  pour cut-out: 2510,1175 2967.5,1175 2967.5,830 2927.5,790 2510,790
  pour cut-out: 300,1065 1030,1065 1030,535 300,535
Inner Layer 2:
  pour cut-out: 2510,1175 2967.5,1175 2967.5,790 2510,790
  pour cut-out: 300,1065 1030,1065 1030,535 300,535
Bottom Layer:
  pour cut-out: 2510,1142.5 2967.5,1142.5 2967.5,832.5 2510,832.5
  pour cut-out: 300,1065 1030,1065 1030,535 300,535
  text ".Layer_Name" at 377,-983.49 h60

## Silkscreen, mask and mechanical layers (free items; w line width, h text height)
Top Overlay:
  lines w7: 1290,277.5 1300,287.5 1300,410 ; 1290,482.5 1300,472.5 1300,410 ; 1435,562.5 1410,537.5 1410,487.5 1332.5,410 1300,410 ; 1715,430 1725,420 1800,420 1815,405 1975,405 ; 1975,300 1975,520 2095,520 2095,300 1975,300
  lines w25: 310,250 2950,250 ; 310,260 310,2275 2950,2275 ; 2950,260 2950,982.5 ; 2950,980 2952.5,2270
  text ".PRJ_Title" at 1007.5,2415 h50
  text "8VDC TO 18VDC" at 177.5,1590 h30 r90
  text "INPUT VOLTAGE RANGE" at 110,1585 h30 r90
  text "2V TO 12V" at 3130,1375 h30 r90
  text "OUTPUT VOLTAGE RANGE" at 3065,1372.5 h30 r90
  text "Iout = 3A Max." at 3192.5,1372.5 h30 r90
  text "VIN" at 40,1042.5 h50
  text "GND" at 35,480 h50
  text "SHUTDOWN" at 610,105 h40
  text "MADE IN USA" at 2407.5,77.5 h40
  text "PWM" at 1425,72.5 h40 r90
  text "IMON" at 1925,62.5 h40 r90
  text "SYNC" at 1175,55 h40 r90
  text "IADJ" at 1670,55 h40 r90
  text ".Layer_Name" at 377,-983.49 h60
Bottom Overlay:
  text ".Layer_Name" at 377,-983.49 h60
Top Paste:
  text ".Layer_Name" at 377,-983.49 h60
Bottom Paste:
  text ".Layer_Name" at 377,-983.49 h60
Top Solder:
  rectangle: 1615,807.5 1795,942.5
  region: 1742.5,1550 1610,1550 1610,1350 1742.5,1350
  rectangle: 450,1282.5 550,1425
  rectangle: 450,1575 550,1725
  region: 925,1800 925,1950 716.93,1950 716.93,1800
  region: 1425,1800 1425,1950 1216.93,1950 1216.93,1800
  region: 1800,1850 1600,1850 1600,1629.92 1800,1629.92
  region: 2157.5,2055 2007.5,2055 2007.5,1846.93 2157.5,1846.93
  region: 2157.5,1563.07 2007.5,1563.07 2007.5,1355 2157.5,1355
  region: 2474.92,2155 2474.92,1955 2675,1955 2675,2155
  region: 2270.89,2130 2270.89,1980 2375,1980 2375,2130
  text ".Layer_Name" at 377,-983.49 h60
  text ".Layer_Name" at 377,-983.49 h60
Bottom Solder:
  rectangle: 1505,827.5 1645,925
  text ".Layer_Name" at 377,-983.49 h60
Drill Guide:
  text ".Layer_Name" at 377,-983.49 h60
M1 Board Outline:
  lines w10: 0,0 0,2500 3300,2500 3300,0 0,0
  text ".Layer_Name" at 377,-983.49 h60
M2 Board Dimensions:
  text ".Layer_Name" at 377,-983.49 h60
M3 3D STEP Top:
  text ".Layer_Name" at 377,-983.49 h60
M4 3D STEP Bottom:
  text ".Layer_Name" at 377,-983.49 h60
M5 Assembly Top:
  lines w10: -492,-1055.17 6108,-1055.17 ; -492,-851.83 6110,-851.83 ; -492,-648.5 -492,-1258.5 3513,-1258.5 6110,-1258.5 6110,-648.5 -491.5,-648.5 -491.5,-1258.5 1084,-1258.5 ; 1973,-1258.5 1973,-648.5 ; 3240,-851.83 3240,-648.5 ; 4080,-851.83 4080,-648.5 ; 4702,-1265 4702,-1062.17
  text "COMPONENTS MARKED 'DNP' SHOULD NOT BE POPULATED." at 953.5,-443.5 h60
  text "ASSEMBLY VARIANT:" at 953,-559 h60
  text ".VariantName" at 1989,-559 h60
  text "PCB VIEWED FROM TOP SIDE" at -428.5,-780.67 h60
  text "BOARD #:" at 2048,-780.67 h60
  text ".PRJ_Number" at 2593.5,-780.67 h60
  text "REV:" at 3438,-780.67 h60
  text ".PCB_Rev" at 3729.5,-780.67 h60
  text "SVN REV:" at 4276,-780.67 h60
  text ".VersionControl_RevNumber" at 4782,-780.67 h60
  text "PLOT NAME =" at -428.5,-1189.34 h60
  text ".plot_File_Name" at 377,-1189.34 h60
  text "GENERATED    :" at 2050,-1189.34 h60
  text ".Print_Date" at 2919.5,-1189.34 h60
  text ".Print_Time" at 3648.5,-1189.34 h60
  text "TEXAS INSTRUMENTS" at 4913,-1189.34 h60
M6 Assembly Bottom:
  lines w10: -492.5,-852.33 6109.5,-852.33 ; -490.5,-1055.67 6109.5,-1055.67 ; 915.5,-1265.5 915.5,-1062.67 ; 1537.5,-852.33 1537.5,-649 ; 2377.5,-852.33 2377.5,-649 ; 3644.5,-1259 3644.5,-649 ; 4533.5,-1259 6109,-1259 6109,-649 -492.5,-649 -492.5,-1259 2104.5,-1259 6109.5,-1259 6109.5,-649
  text "COMPONENTS MARKED 'DNP' SHOULD NOT BE POPULATED." at 5902,-443 h60
  text ".VariantName" at 4858,-559 h60
  text "ASSEMBLY VARIANT:" at 5897,-559 h60
  text ".VersionControl_RevNumber" at 835.5,-781.17 h60
  text "SVN REV:" at 1341.5,-781.17 h60
  text ".PCB_Rev" at 1888,-781.17 h60
  text "REV:" at 2179.5,-781.17 h60
  text ".PRJ_Number" at 3024,-781.17 h60
  text "BOARD #:" at 3569.5,-781.17 h60
  text "PCB VIEWED FROM BOTTOM SIDE" at 6046,-781.17 h60
  text "TEXAS INSTRUMENTS" at 704.5,-1189.84 h60
  text ".Print_Time" at 1969,-1189.84 h60
  text ".Print_Date" at 2698,-1189.84 h60
  text "GENERATED    :" at 3567.5,-1189.84 h60
  text ".plot_File_Name" at 5240.5,-1189.84 h60
  text "PLOT NAME =" at 6046,-1189.84 h60
M9 Title Sheet:
  drawing of 57 lines, arcs and shapes, not listed
  text "1" at 539.84,7911.5 h70
  text "2" at 3035.5,7911.5 h70
  text "3" at 5524.84,7911.5 h70
  text "4" at 8031.51,7911.5 h70
  text "5" at 10530.5,7911.5 h70
  text "6" at 13035.5,7911.5 h70
  text "A" at -616.5,6768.5 h70
  text "A" at 14183.5,6768.5 h70
  text "B" at -616.5,4388.5 h70
  text "B" at 14183.5,4388.5 h70
  text "C" at -616.5,2013.5 h70
  text "C" at 14183.5,2013.5 h70
  text "PROJECT TITLE:" at 11143.5,152.5 h45
  text ".PRJ_Title" at 11193.5,19.17 h70
  text "DESIGNED FOR:" at 11143.5,-148.5 h45
  text ".PRJ_Customer" at 11193.5,-288.5 h70
  text "D" at -616.5,-356.5 h70
  text "D" at 14183.5,-356.5 h70
  text "FILE NAME:" at 11143.5,-448.5 h45
  text ".PCB_File_Name_No_Path" at 11193.5,-568.5 h70
  text "Texas Instruments (TI) and/or its licensors do not warrant the accuracy or completeness of this specification" at 6174,-730.34 h45
  text "ENGINEER:" at 11143.5,-738.5 h45
  text "LAYOUT BY:" at 12648.5,-738.5 h45
  text "or any information contained therein. TI and/or its licensors do not warrant that this design will meet" at 6129.01,-843 h45
  text ".PRJ_Engineer" at 11193.5,-893.49 h70
  text ".PCB_Layout" at 12699,-893.49 h70
  text "the specifications, will be suitable for your application or fit for any particular purpose, or will operate in" at 6129.01,-955.67 h45
  text ".Layer_Name" at 377,-983.49 h60
  text "ALTIUM DESIGNER VERSION:" at 12648.5,-1048.5 h45
  text "an implementation. TI and/or its licensors do not warrant that the design is production worthy. You should" at 6129.01,-1068.33 h45
  text "completely validate and test your design implementation to confirm the system functionality for your application." at 6174,-1181 h45
  text ".print_Scale" at 11193.5,-1181.83 h70
  text ".Application_BuildNumber" at 12699,-1181.83 h70
  text "1" at 539.84,-1388.5 h70
  text "2" at 3035.5,-1388.5 h70
  text "3" at 5524.84,-1388.5 h70
  text "4" at 8031.51,-1388.5 h70
  text "5" at 10530.5,-1388.5 h70
  text "6" at 13035.5,-1388.5 h70
M10 Fab Notes:
  drawing of 185 lines, arcs and shapes, not listed
  text "DESIGN INFORMATION" at 12181.02,5785 h60
  text "MIN. TRACK WIDTH:" at 11536.46,5605 h60
  text "10" at 12632.7,5605 h60
  text "MIL" at 12787.46,5605 h60
  text "MIN. CLEARANCE:" at 11536.46,5473 h60
  text "0.2" at 12572.7,5473 h60
  text "mm" at 12787.46,5473 h60
  text "MIN. VIA PAD SIZE:" at 11536.46,5341 h60
  text "20" at 12602.71,5341 h60
  text "MIL" at 12787.46,5341 h60
  text "0.05mm (2MIL)" at 12231.46,5199.29 h60
  text "MINIMUM ANNULAR RING" at 11207.23,5195 h60
  text "EXTERNAL" at 12939.46,5195 h60
  text "PER" at 11407.23,5077 h60
  text "IPC-D-275 CLASS 2 LEVEL C" at 11627.23,5077 h60
  text "MIL, HOLES" at 13115.46,4964.71 h60
  text "+/-" at 12723,4964 h60
  text "+/-" at 13577,4964 h60
  text "REGISTRATION TOLERANCES:" at 11207.23,4959 h60
  text "METAL" at 12407,4959 h60
  text "5" at 12983.2,4959 h60
  text "3" at 13816.2,4959 h60
  text "MIL" at 13932.46,4959 h60
  text "4 Layer Board" at 11624,4769 h70
  text "MATERIAL:" at 11132.46,4749.54 h60
  text "FR-4 High Tg" at 12118.9,4609.21 h60
  text "FR-408" at 11553.46,4600.64 h60
  text "OTHER" at 13041.46,4600.64 h60
  text "X" at 11965,4590 h60
  text "62 MIL (1.6mm) +/-10%" at 11873.56,4437.92 h60
  text "THICKNESS:" at 11207.23,4433.64 h60
  text "X" at 11745.4,4433.64 h60
  text "OTHER" at 13158.46,4433.64 h60
  text "TOLERANCE:" at 11207.23,4275.64 h60
  text "X" at 12046.53,4275.64 h60
  text "ANSI IPC-6012 TYPE 3 CLASS 2" at 12233.48,4275.64 h60
  text "OTHER +/-" at 12233.46,4119.64 h60
  text "BOW & TWIST:" at 11207.23,3962.64 h60
  text "X" at 12046.53,3962.64 h60
  text "ANSI IPC-6012 TYPE 3 CLASS 2" at 12233.48,3962.64 h60
  text "OTHER +/-" at 12233.46,3804.13 h60
  text "DRILLING:" at 11132.46,3665.64 h60
  text "REFERENCE:" at 11207.23,3548.64 h60
  text "X" at 11855.46,3548.64 h60
  text "AS SHOWN" at 12042.46,3548.64 h60
  text "X" at 12756.46,3548.64 h60
  text "NC_DRILL FILES" at 12893.46,3548.64 h60
  text "PTH MIN COPPER THICKNESS:" at 11207.23,3390.64 h60
  text "X" at 12557.46,3390.64 h60
  text "1MIL" at 12694.46,3390.64 h60
  text "OTHER" at 13191.46,3390.64 h60
  text "BOARD FINISH:" at 11132.46,3231.64 h60
  text "SILKSCREEN:" at 11287.68,3113.64 h60
  text "X" at 12236.46,3113.64 h60
  text "TOP" at 12362.46,3113.64 h60
  text "BOTTOM" at 12873.46,3113.64 h60
  text "SILKSCREEN COLOR:" at 11287.68,2946.64 h60
  text "X" at 12235.42,2946.64 h60
  text "WHITE" at 12362.46,2946.64 h60
  text "OTHER" at 12873.46,2946.64 h60
  text "SOLDER RESIST COLOR:" at 11287.68,2776.64 h60
  text "X" at 11855.42,2617.44 h60
  text "GREEN" at 11982.46,2617.44 h60
  text "BLUE" at 12573.46,2617.44 h60
  text "OTHER" at 13111.46,2617.44 h60
  text "IMMERSION GOLD (ENIG)" at 12193.46,2428.92 h60
  text "ENEPIG" at 13531,2425.64 h60
  text "SURFACE FINISH:" at 11132.46,2424.64 h60
  text "IMM. TIN/SILVER OR EQUIV" at 11462,2267.64 h60
  text "OTHER" at 12893.46,2267.64 h60
  text "X" at 11295,2265 h60
  text "ARRAY/PANEL:" at 11132.46,2088.64 h60
  text "X" at 12024,2088 h60
  text "CUT AND TRIM PER MECH LAYER 1" at 12193.46,2084.35 h60
  text "N.C. ROUTE" at 12193.46,1932.64 h60
  text "V. SCORE" at 13059.46,1932.64 h60
  text "CERTIFICATION:" at 11132.46,1795.64 h60
  text "MATERIALS AND WORKMANSHIP FOR ALL PCBS" at 11857.46,1795.64 h60
  text "TO MEET OR EXCEED THE REQUIREMENTS OF:" at 11857.46,1697.64 h60
  text "X" at 11483.96,1561.13 h60
  text "ANSI IPC-A-600F CLASS ->" at 11622.96,1561.13 h60
  text "X" at 13262.02,1561.13 h60
  text "2" at 13380.96,1561.14 h60
  text "1" at 13065.96,1559.64 h60
  text "3" at 13734.96,1559.64 h60
  text "X" at 11486.02,1401.64 h60
  text "UL 94V-0" at 11622.96,1401.64 h60
  text "X" at 12298.02,1401.64 h60
  text "RoHS" at 12434.96,1401.64 h60
  text "OTHER" at 13079.36,1401.64 h60
  text "ADDITIONAL REQUIREMENTS:" at 11132.46,1260.64 h60
  text "MICROSECTION:" at 11207.23,1145.64 h60
  text "YES" at 12112.96,1145.64 h60
  text "REQUIRED" at 12974.46,989.49 h60
  text "BARE BOARD ELEC. TEST:" at 11207.23,986.64 h60
  text "NONE" at 12512.96,986.64 h60
  text "PER ORDER" at 13566.46,986.64 h60
  text "X" at 12384,983 h60
  text "MANUFACTURER'S UL:" at 11207.23,829.64 h60
  text "RAIL" at 12372.96,825.35 h60
  text "METAL" at 12864.77,825.35 h60
  text "X" at 13240,825 h60
  text "SILK" at 13376.46,825.35 h60
  text ".Layer_Name" at 377,-983.49 h60
M11 Gerber Information:
  lines w10: -492,-1055.17 6108,-1055.17 ; -492,-851.83 6110,-851.83 ; -492,-648.5 -492,-1258.5 3513,-1258.5 6110,-1258.5 6110,-648.5 -491.5,-648.5 -491.5,-1258.5 1084,-1258.5 ; 1973,-1258.5 1973,-648.5 ; 3240,-851.83 3240,-648.5 ; 4080,-851.83 4080,-648.5 ; 4702,-1265 4702,-1062.17
  text "ALL ARTWORK VIEWED FROM TOP SIDE" at -428.5,-780.67 h60
  text "BOARD #:" at 2048,-780.67 h60
  text ".PRJ_Number" at 2593.5,-780.67 h60
  text "REV:" at 3438,-780.67 h60
  text ".PCB_Rev" at 3729.5,-780.67 h60
  text "SVN REV:" at 4276,-780.67 h60
  text ".VersionControl_RevNumber" at 4782,-780.67 h60
  text "LAYER NAME =" at -428.5,-983.49 h60
  text "PLOT NAME =" at -428.5,-1189.34 h60
  text ".plot_File_Name" at 377,-1189.34 h60
  text "GENERATED    :" at 2050,-1189.34 h60
  text ".Print_Date" at 2919.5,-1189.34 h60
  text ".Print_Time" at 3648.5,-1189.34 h60
  text "TEXAS INSTRUMENTS" at 4913,-1189.34 h60
M12 Stackup:
  drawing of 295 lines, arcs and shapes, not listed
  text "Layer" at 9577.5,7715 h60
  text "Name" at 9987.41,7715 h60
  text "Material" at 10917.16,7715 h60
  text "Thickness" at 11776.92,7715 h60
  text "Constant" at 12426.76,7715 h60
  text "Board Layer Stack" at 12996.62,7715 h60
  text "1" at 9577.5,7595 h60
  text "Top Overlay" at 9987.41,7595 h60
  text "2" at 9577.5,7475 h60
  text "Top Solder" at 9987.41,7475 h60
  text "Solder Resist" at 10917.16,7475 h60
  text "0.40mil" at 11776.92,7475 h60
  text "3.5" at 12426.76,7475 h60
  text "3" at 9577.5,7355 h60
  text "Top Layer" at 9987.41,7355 h60
  text "Copper" at 10917.16,7355 h60
  text "1.40mil" at 11776.92,7355 h60
  text "4" at 9577.5,7235 h60
  text "Dielectric1" at 9987.41,7235 h60
  text "8.00mil" at 11776.92,7235 h60
  text "4.2" at 12426.76,7235 h60
  text "5" at 9577.5,7115 h60
  text "Inner Layer 1" at 9987.41,7115 h60
  text "Copper" at 10917.16,7115 h60
  text "2.80mil" at 11776.92,7115 h60
  text "6" at 9577.5,6995 h60
  text "Dielectric 3" at 9987.41,6995 h60
  text "36.80mil" at 11776.92,6995 h60
  text "4.2" at 12426.76,6995 h60
  text "7" at 9577.5,6875 h60
  text "Inner Layer 2" at 9987.41,6875 h60
  text "Copper" at 10917.16,6875 h60
  text "2.80mil" at 11776.92,6875 h60
  text "8" at 9577.5,6755 h60
  text "Dielectric 2" at 9987.41,6755 h60
  text "8.00mil" at 11776.92,6755 h60
  text "4.2" at 12426.76,6755 h60
  text "9" at 9577.5,6635 h60
  text "Bottom Layer" at 9987.41,6635 h60
  text "Copper" at 10917.16,6635 h60
  text "1.40mil" at 11776.92,6635 h60
  text "10" at 9577.5,6515 h60
  text "Bottom Solder" at 9987.41,6515 h60
  text "Solder Resist" at 10917.16,6515 h60
  text "0.40mil" at 11776.92,6515 h60
  text "3.5" at 12426.76,6515 h60
  text "11" at 9577.5,6395 h60
  text "Bottom Overlay" at 9987.41,6395 h60
  text ".Layer_Name" at 377,-983.49 h60
M13 Component Bodies Top:
  text ".Layer_Name" at 377,-983.49 h60
M14 Component Bodies Bottom:
  text ".Layer_Name" at 377,-983.49 h60
M15 Courtyards Top:
  text ".Layer_Name" at 377,-983.49 h60
M16 Courtyards Bottom:
  text ".Layer_Name" at 377,-983.49 h60
Drill Drawing:
  circle w10: c6473.82,2231.02 r16.6
  circle w10: c6473.82,2231.02 r27.67
  lines w7: 3265,2200 3535,2200 ; 3050,1997.5 3050,2420 3240,2420 3240,1997.5 3050,1997.5
  lines w10: 6446.16,1705.35 6473.82,1719.18 6501.49,1705.35 6487.66,1733.02 6501.49,1760.68 6473.82,1746.85 6446.16,1760.68 6459.99,1733.02 6446.16,1705.35 ; 6446.16,1843.68 6459.99,1843.68 6459.99,1829.85 6487.66,1829.85 6487.66,1843.68 6501.49,1843.68 6501.49,1871.35 6487.66,1871.35 6487.66,1885.18 6459.99,1885.18 6459.99,1871.35 6446.16,1871.35 6446.16,1843.68 ; 6446.16,1968.18 6459.99,1968.18 6473.82,1954.35 6487.66,1968.18 6501.49,1968.18 6487.66,1982.02 6501.49,1995.85 6487.66,1995.85 6473.82,2009.68 6459.99,1995.85 6446.16,1995.85 6459.99,1982.02 6446.16,1968.18 ; 6446.16,2078.85 6501.49,2078.85 6501.49,2134.18 6446.16,2134.18 6446.16,2078.85 ; 6457.23,2089.92 6490.43,2089.92 6490.43,2123.12 6457.23,2123.12 6457.23,2089.92
  lines w12: 6396,1668 8374.44,1668 ; 6396,2290.5 8374.44,2290.5 ; 6734.01,1543.5 6734.01,2415 ; 7066.17,1543.5 7066.17,2415 ; 7702.65,1543.5 7702.65,2415 ; 7961.85,1543.5 7961.85,2415 ; 6396,1543.5 8374.44,1543.5 8374.44,2415 6396,2415 6396,1543.5
  text "Symbol" at 6470.7,2327.85 h72
  text "Quantity" at 6771.36,2327.85 h72
  text "Finished Hole Size" at 7103.52,2327.85 h72
  text "Plated" at 7740,2327.85 h72
  text "Hole Type" at 7999.2,2327.85 h72
  text "6" at 6771.36,2203.35 h60
  text "8.00mil (0.203mm)" at 7103.52,2203.35 h60
  text "PTH" at 7740,2203.35 h60
  text "Round" at 7999.2,2203.35 h60
  text "PLACE MFGRS LOGO, UL FLAMMABILITY RATING, Tg TEMP, AND DATE CODE HERE BOTTOM SIDE" at 3567.5,2187.5 h60
  text "162" at 6771.36,2078.85 h60
  text "12.00mil (0.305mm)" at 7103.52,2078.85 h60
  text "PTH" at 7740,2078.85 h60
  text "Round" at 7999.2,2078.85 h60
  text "5" at 6771.36,1954.35 h60
  text "40.00mil (1.016mm)" at 7103.52,1954.35 h60
  text "PTH" at 7740,1954.35 h60
  text "Round" at 7999.2,1954.35 h60
  text "3" at 6771.36,1829.85 h60
  text "43.31mil (1.100mm)" at 7103.52,1829.85 h60
  text "PTH" at 7740,1829.85 h60
  text "Round" at 7999.2,1829.85 h60
  text "5" at 6771.36,1705.35 h60
  text "98.43mil (2.500mm)" at 7103.52,1705.35 h60
  text "PTH" at 7740,1705.35 h60
  text "Round" at 7999.2,1705.35 h60
  text "181 Total" at 6771.36,1580.85 h60
  text ".Layer_Name" at 377,-983.49 h60

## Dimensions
0,0 to 0,2500 on M2 Board Dimensions
0,0 to 3300,0 on M2 Board Dimensions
